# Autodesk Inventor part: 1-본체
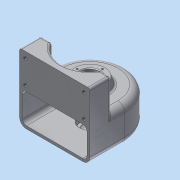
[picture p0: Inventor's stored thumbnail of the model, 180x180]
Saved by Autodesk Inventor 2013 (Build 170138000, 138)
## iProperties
Created: 2015-02
Part Number: 1-본체
Material: 알루미늄 6061
Document SubType Name: Modeling
Designer: Administrator
Density: 2.40731 g/cm^3
Mass: 511.244 g
Surface Area: 706.56 cm^2
Volume: 212.371 cm^3
Author: Administrator
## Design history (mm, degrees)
sketch "스케치1"
  geometry: L1 (50, 0)-(50, -50); L2 (50, -50)-(-50, -50); L3 (-50, -50)-(-50, 0); A1 r 50 centre (0, 0) between (50, 0) and (-50, 0); 1 further point
  constraints: 6 end point, 2 point on circle, 2 tangent, 1 centre point, 1 coincident, 1 parallel, 1 perpendicular, 1 vertical
  dimensions: "d0" = 50 radius of A1; "d2" = 50 distance from line of L2 point (0, 0)
extrude "돌출1" new body sketch "스케치1" distance "d3" = 50; taper "d4" = 0 deg
feature "쉘1" dims "d5" = 4
sketch "스케치2"
  geometry: C1 r 20 at (0, 0); A1 r 50 centre (0, 0) between (50, 0) and (-50, 0) reference
  constraints: 1 centre point, 1 coincident
  dimensions: "d6" = 40 diameter of C1
extrude "돌출2" join sketch "스케치2" distance "d8" = 9; taper "d9" = 0 deg
sketch "스케치3"
  geometry: C1 r 25 at (0, 0); A1 r 50 centre (0, 0) between (50, 0) and (-50, 0) reference
  constraints: 1 centre point, 1 coincident
  dimensions: "d10" = 50 diameter of C1
extrude "돌출3" join sketch "스케치3" distance "d12" = 10; taper "d13" = -20 deg
hole "구멍1" diameter "d16" = 20; stored, may be unused: countersink angle "d20" = 90 deg, drill point angle "d22" = 0 deg; dims "d14" = 10, "d15" = 10, "d17" = 6, "d18" = 28, "d19" = 8, "d21" = 10
hole "구멍2" diameter "d25" = 20; stored, may be unused: countersink angle "d29" = 90 deg, drill point angle "d31" = 0 deg; dims "d23" = 10, "d24" = 10, "d26" = 6, "d27" = 28, "d28" = 10, "d30" = 14
node "작업 평면1"
sketch "스케치4"
  geometry: L1 (-50, -50)-(50, -50) reference; L2 (50, -50)-(50, 0) reference; L3 (-50, 0)-(-50, -50) reference; L4 (50, -50)-(50, -20); L5 (34.641, -20)-(50, -20); L6 (-50, -50)-(-50, -20); L7 (-50, -20)-(-34.641, -20); A1 r 40 centre (0, 0) between (-34.641, -20) and (34.641, -20); 1 further point
  constraints: 8 end point, 2 perpendicular, 2 point on circle, 2 point on line, 1 centre point, 1 coincident, 1 collinear
  dimensions: "d33" = 40 radius of A1; "d35" = 30 distance between parallel lines of L1 L5
extrude "돌출4" join sketch "스케치4" stored distance "d36" = 10; taper "d37" = 0 deg
sketch "스케치5"
  geometry: L1 (100, 0)-(100, 95) reference; L2 (0, 95)-(100, 95) reference; L3 (8.25, 86)-(91.75, 86); L4 (91.75, 86)-(91.75, 53); L5 (91.75, 53)-(8.25, 53); L6 (8.25, 53)-(8.25, 86); L7 (8.25, 86)-(91.75, 53); L8 (91.75, 86)-(8.25, 53); 6 further points
  constraints: 12 end point, 4 coincident, 2 midpoint, 2 parallel, 1 horizontal, 1 perpendicular
  dimensions: "d38" = 33 distance of L3.end L4.end; "d40" = 83.5 distance of L3.start L3.end; "d41" = 9 distance between parallel lines of L2 L3; "d42" = 8.25 distance between parallel lines of L4 L1
hole "구멍3" sketch "스케치5" at (91.75, 86), (8.25, 86), (8.25, 53), (91.75, 53) diameter "d43" = 5.134; stored, may be unused: countersink angle "d47" = 90 deg, drill point angle "d49" = 118 deg; dims "d44" = 10, "d45" = 28, "d46" = 10, "d48" = 13
sketch "스케치6"
  geometry: C1 r 14 at (0, 0) reference; C2 r 21.36 at (0, 0) reference; A1 r 18 centre (0, 0) between (0, 18) and (-18, 0); 2 further points
  constraints: 4 point on circle, 2 horizontal alignment, 2 vertical alignment, 1 centre point, 1 coincident
  dimensions: "d50" = 36 diameter of A1
hole "구멍4" sketch "스케치6" at (0, 18), (-18, 0), (0, -18), (18, 0) diameter "d52" = 2.459; stored, may be unused: countersink angle "d56" = 90 deg, drill point angle "d58" = 118 deg; dims "d53" = 6, "d54" = 28, "d55" = 10, "d57" = 9
node "작업 평면2"
sketch "스케치7"
  geometry: L1 (50, 0)-(-50, 0) reference; 3 further points
  constraints: 1 midpoint, 1 vertical alignment, 1 other
  dimensions: "d59" = 25 distance from line of point (0, 25) L1
feature "엠보싱1" sketch "스케치7" dims "d0" = 50, "d2" = 50, "d60" = 0.5, "d61" = 0
chamfer "모따기1" distance "d62" = 1; stored, may be unused: second distance "d63" = 2, angle "d64" = 45 deg
fillet "모깎기1" dims "d65" = 0.3, "d66" = 3
fillet "모깎기2" dims "d67" = 10, "d68" = 6
fillet "모깎기3" dims "d69" = 3
fillet "모깎기4" dims "d70" = 3
node "솔리드1"
other parameters: "d32" = -95
